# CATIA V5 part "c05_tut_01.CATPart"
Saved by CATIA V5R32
Part number: Part1
Bounding box of the stored display mesh (mm): x -20 to 20, y 0 to 95, z 0 to 40
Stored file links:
  D:\PROJECTS\Project 2022\CATIA V5 6R 2022\Resources\Tutorial Files\c05_catia_v5_6r2022_tut\c05_tut_01.CATPart
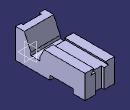
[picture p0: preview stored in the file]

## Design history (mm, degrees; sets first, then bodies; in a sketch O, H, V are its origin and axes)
Body1 (main body)
  Sketch1 on yz-plane, origin (0, 0, 0), H (0, 1, 0), V (0, 0, 1)
    line L1 (0, 0) -> (0, 40)
    line L2 (0, 40) -> (12, 40)
    point P2 (12, 40)
    line L3 (12, 40) -> (21, 20)
    point P3 (21, 20)
    line L4 (21, 20) -> (21, 16)
    line L5 (21, 16) -> (33, 16)
    line L6 (33, 16) -> (33, 20)
    point P6 (33, 20)
    line L7 (33, 20) -> (39, 32)
    point P7 (39, 32)
    line L8 (39, 32) -> (95, 32)
    line L9 (95, 32) -> (95, 0)
    line L10 (95, 0) -> (79, 0)
    line L11 (79, 0) -> (79, 6)
    line L12 (79, 6) -> (47, 6)
    line L13 (47, 6) -> (47, 0)
    point P13 (47, 0)
    line L14 (47, 0) -> (0, 0)
    distance L2 L14 = 40
    length L2 = 12
    distance L14 L5 = 16
    distance P3 L5 = 4
    distance L8 P6 = 12
    distance L12 L10 = 6
    distance L11 L9 = 16
    distance L13 L11 = 32
    distance P2 P7 H = 27
    distance L1 L9 = 95
    distance L8 L10 = 32
    distance P7 P6 H = 6
    length L5 = 12
    coincidence: P13 L10, L14 H
    vertical: L13 V, L1 V, L4 V, L6 V, L9 V, L11 V
    horizontal: L14 H, L10 H
  Pad1: profile Sketch1, direction (1, 0, 0), length 20, mirrored extent
  Sketch2 on face of Pad1 from Sketch1.L9, origin (0, 95, 0), H (-1, 0, 0), V (0, 0, 1)
    line L1 (-8, 32) -> (-12.0471, 26)
    line L2 (-12.0471, 26) -> (12.0471, 26)
    line L3 (12.0471, 26) -> (8, 32)
    line L4 (8, 32) -> (-8, 32)
    reference projected line E1 (20, 32) -> (-20, 32) from edge [face of Pad1 from Sketch1.L8 | face of Pad1 from Sketch1.L9]
    reference projected line E2 (20, 0) -> (-20, 0) from edge [face of Pad1 from Sketch1.L9 | face of Pad1 from Sketch1.L10]
    distance E2 L2 = 26
    angle L3 L2 = 56
    length L4 = 16
    horizontal: L2 H, L4 H
    coincidence: L4 E1
    symmetry: L1 L3 V
  Pocket1: profile Sketch2, direction (0, -1, 0), through (limit type 6)
  Sketch3 on face of Pad1 from Sketch1.L9, origin (0, 95, 0), H (-1, 0, 0), V (0, 0, 1)
    line L1 (-6, 26) -> (6, 26)
    line L2 (6, 26) -> (6, 0)
    line L3 (6, 0) -> (-6, 0)
    line L4 (-6, 0) -> (-6, 26)
    point P3 (6, 0)
    reference projected line E1 (-12.0471, 26) -> (12.0471, 26) from edge [face of Pad1 from Sketch1.L9 | face of Pocket1 from Sketch2.L2]
    distance L4 L2 = 12
    horizontal: L1 H, L3 H
    vertical: L2 V, L4 V
    coincidence: P3 H, L1 E1
    symmetry: L4 L2 V
  Pocket2: profile Sketch3, direction (0, -1, 0), length 4
  Sketch4 on face of Pad1 from Sketch1.L1, origin (0, 0, 0), H (1, 0, 0), V (0, 0, 1)
    point P1 (-12.5, 0)
    line L1 (-12.5, 0) -> (12.5, 0)
    line L2 (12.5, 0) -> (12.5, 40)
    line L3 (12.5, 40) -> (-12.5, 40)
    line L4 (-12.5, 40) -> (-12.5, 0)
    reference projected line E1 (-20, 40) -> (20, 40) from edge [face of Pad1 from Sketch1.L1 | face of Pad1 from Sketch1.L2]
    distance L4 L2 = 25
    coincidence: P1 H, L3 E1
    horizontal: L1 H, L3 H
    vertical: L2 V, L4 V
    symmetry: L4 L2 V
  Pocket3: profile Sketch4, direction (0, 1, 0), length 3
